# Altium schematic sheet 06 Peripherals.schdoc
size 400 x 277 mm; Device: default420x297; Symbol: default420x297; Name: default420x297; Size: "A3"; Id: /; File: 06 Peripherals; Sheet: /
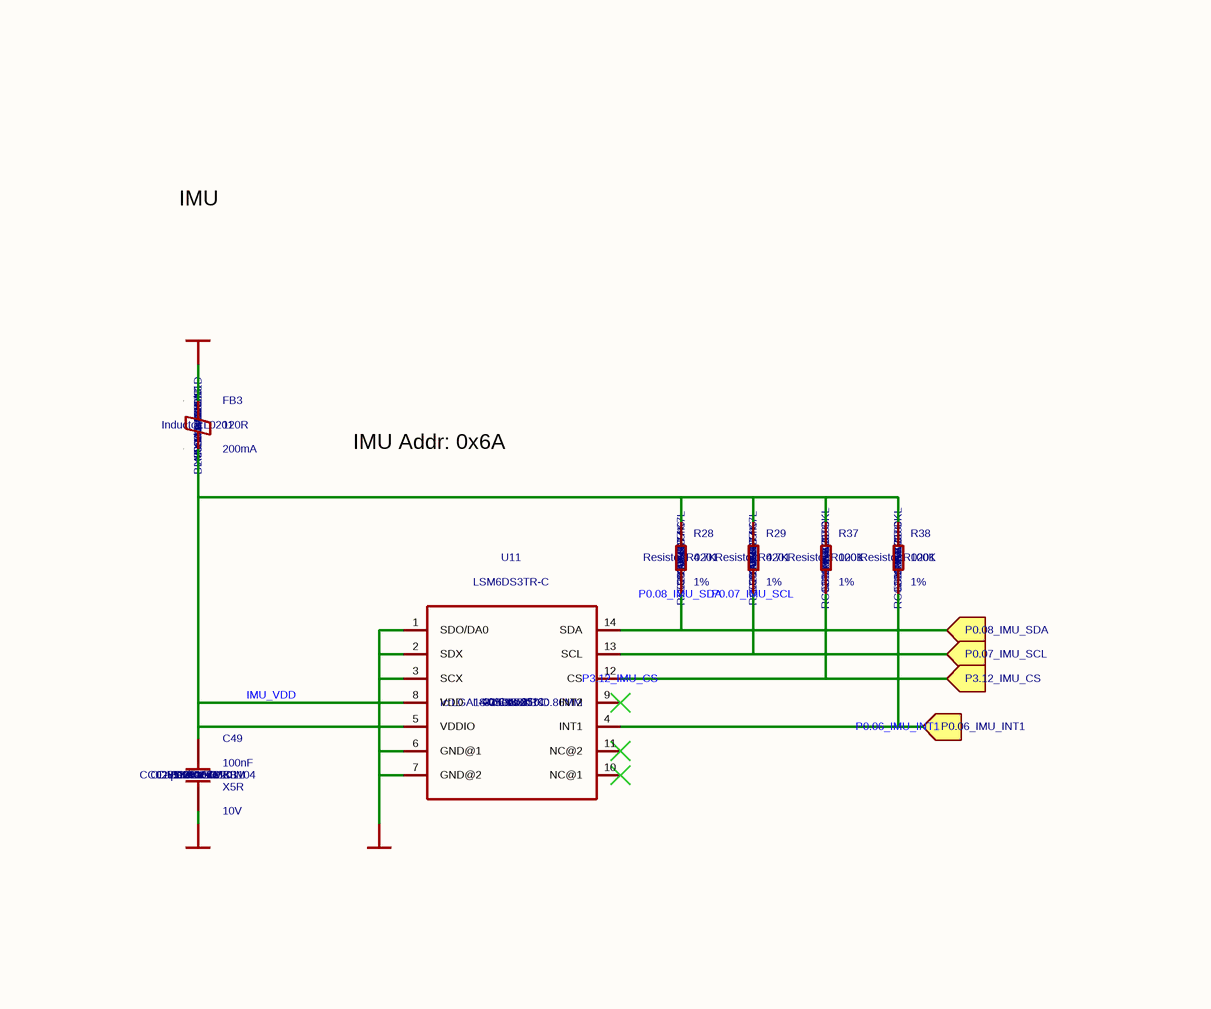
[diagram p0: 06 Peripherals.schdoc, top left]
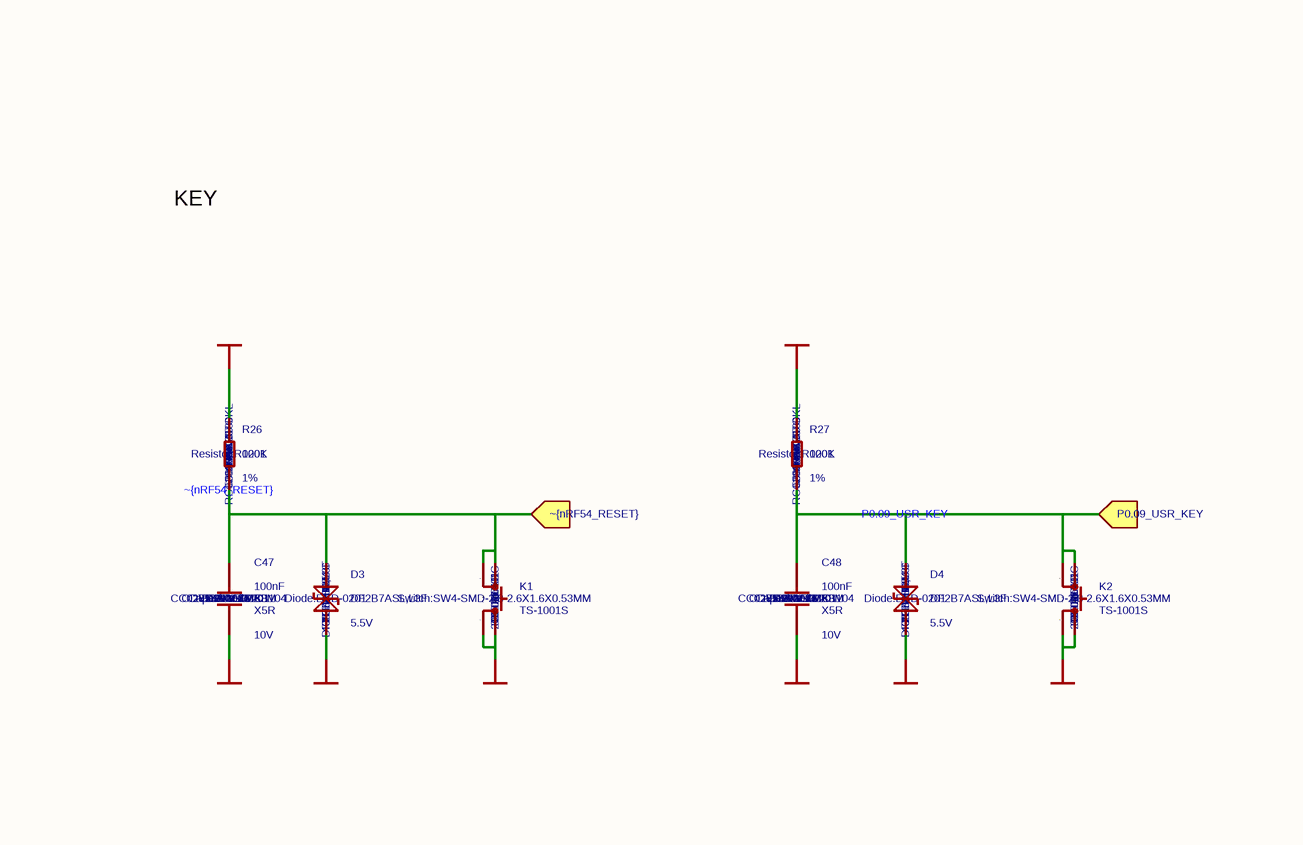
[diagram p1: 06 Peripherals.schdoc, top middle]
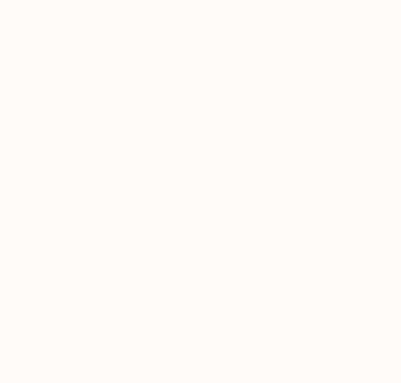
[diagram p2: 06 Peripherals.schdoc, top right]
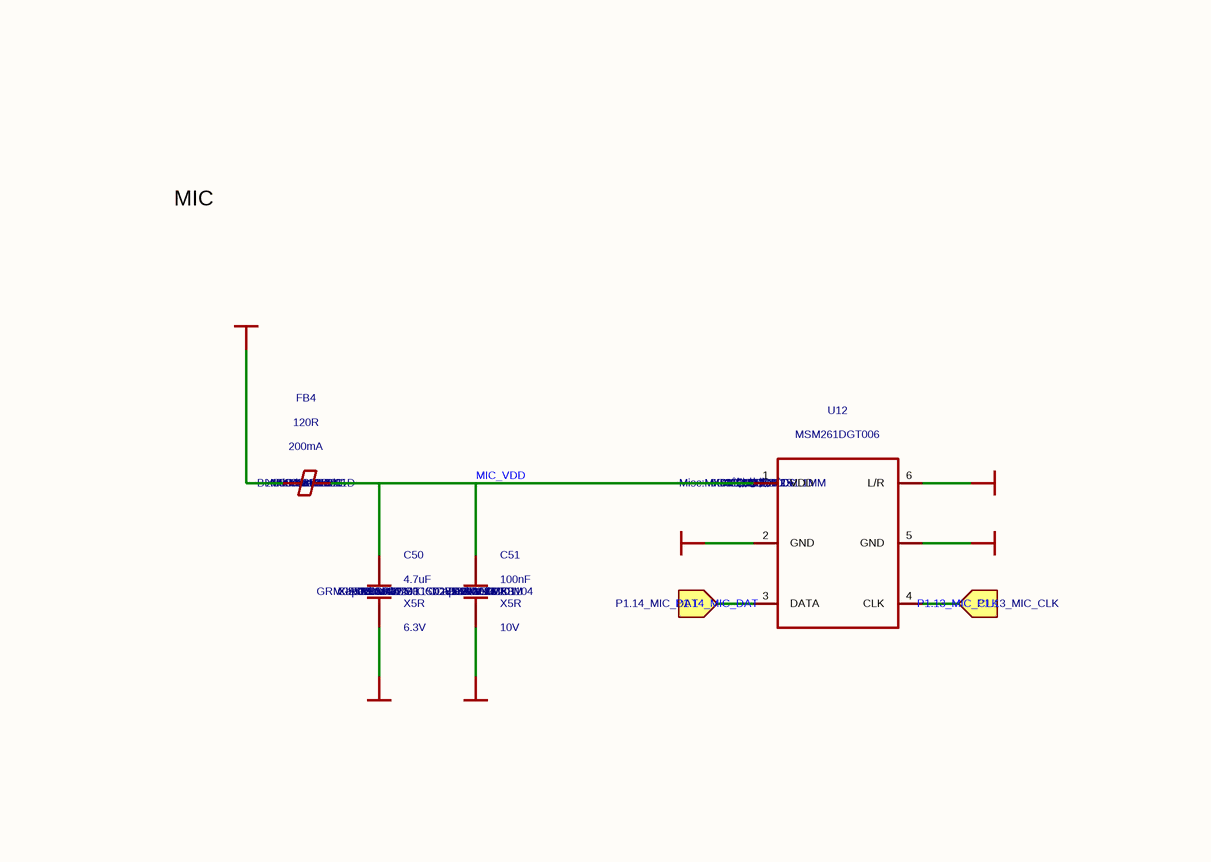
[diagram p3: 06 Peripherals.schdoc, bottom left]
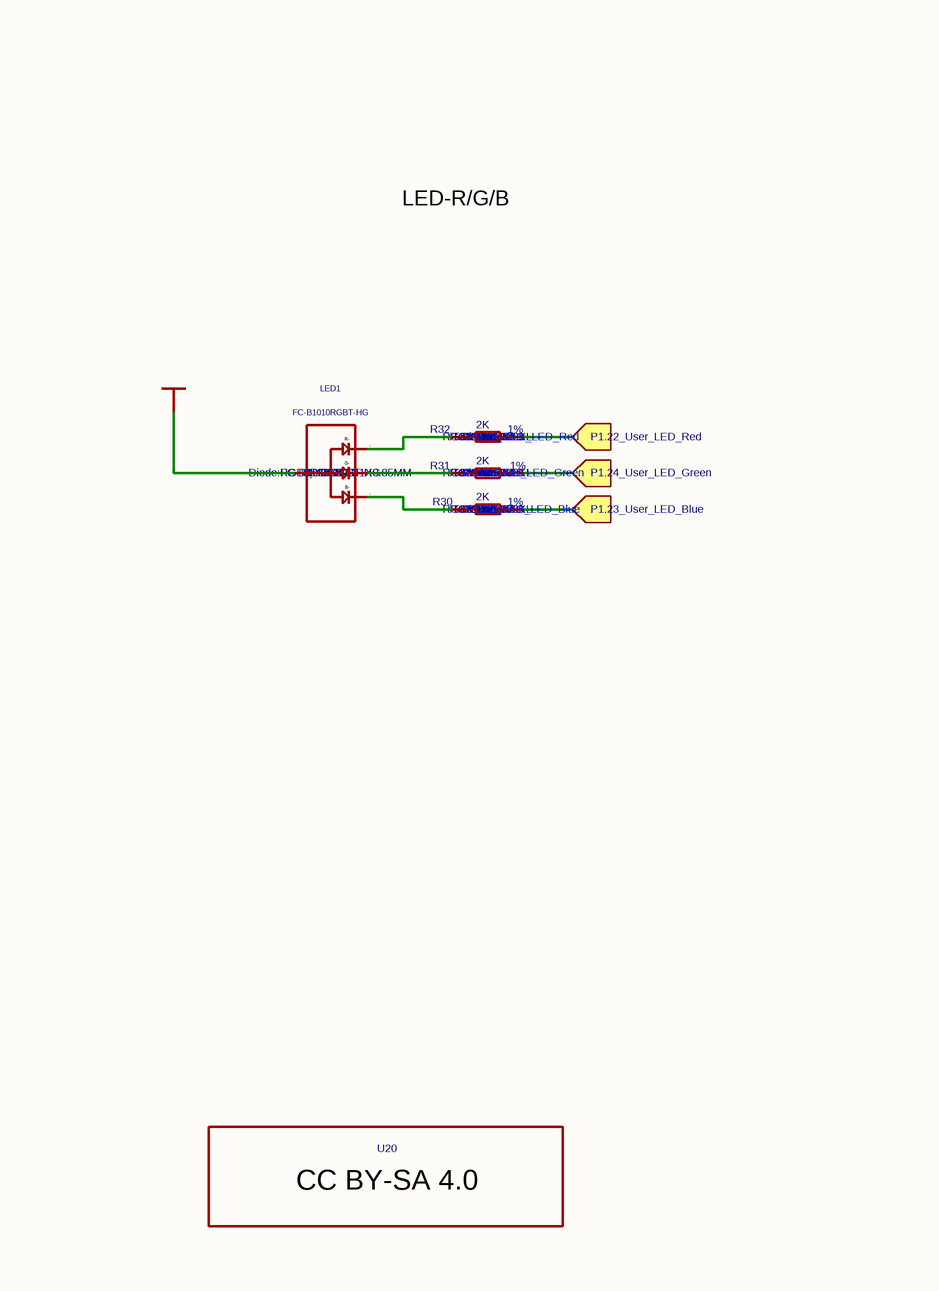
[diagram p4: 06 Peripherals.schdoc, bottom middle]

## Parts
C47  value 100nF  Manufacturer: YAGEO  MPN: CC0201KRX5R6BB104  SKU: 302010271  Dielectric: X5R  Part Type: Ceramic  Voltage Rating: 10V  Status: ODYSSEY-i.MX8M  Temperature: -55°C to 85°C  [Capacitor:C0201]  (hidden comment: Seeed_libdb_Capacitors/CA201100NF-SQS4XQ)
C48  value 100nF  Manufacturer: YAGEO  MPN: CC0201KRX5R6BB104  SKU: 302010271  Dielectric: X5R  Part Type: Ceramic  Voltage Rating: 10V  Status: ODYSSEY-i.MX8M  Temperature: -55°C to 85°C  [Capacitor:C0201]  (hidden comment: Seeed_libdb_Capacitors/CA201100NF-SQS4XQ)
C49  value 100nF  Manufacturer: YAGEO  MPN: CC0201KRX5R6BB104  SKU: 302010271  Dielectric: X5R  Part Type: Ceramic  Voltage Rating: 10V  Status: ODYSSEY-i.MX8M  Temperature: -55°C to 85°C  [Capacitor:C0201]  (hidden comment: Seeed_libdb_Capacitors/CA201100NF-SQS4XQ)
C50  value 4.7uF  Manufacturer: Murata  MPN: GRM035R60J475ME15D  SKU: 302013247  Dielectric: X5R  Part Type: Ceramic  Voltage Rating: 6.3V  Status: XIAO ESP32 S3  Temperature: -55°C to 85°C  [Capacitor:C0201]  (hidden comment: Seeed_libdb_Capacitors/CA20147UF0-SN7236)
C51  value 100nF  Manufacturer: YAGEO  MPN: CC0201KRX5R6BB104  SKU: 302010271  Dielectric: X5R  Part Type: Ceramic  Voltage Rating: 10V  Status: ODYSSEY-i.MX8M  Temperature: -55°C to 85°C  [Capacitor:C0201]  (hidden comment: Seeed_libdb_Capacitors/CA201100NF-SQS4XQ)
D3  value DF2B7ASL,L3F  Manufacturer: TOSHIBA  SKU: 304060494  Part Type: ESD  Rating: 5.5V  Temperature: -40°C to 125°C  [Diode:ESD-0201]  (hidden comment: Seeed_libdb_Diode/DI201DF2B7-5S4UTU)
D4  value DF2B7ASL,L3F  Manufacturer: TOSHIBA  SKU: 304060494  Part Type: ESD  Rating: 5.5V  Temperature: -40°C to 125°C  [Diode:ESD-0201]  (hidden comment: Seeed_libdb_Diode/DI201DF2B7-5S4UTU)
FB3  value 120R  Manufacturer: Murata  MPN: BLM03AG121SN1D  SKU: 303030259  Part Type: Ferrite Bead  Rating: 200mA  Status: XIAO nRF54L15  Temperature: -55°C to 125°C  [Inductor:L0201]  (hidden comment: Seeed_libdb_Ferrite Bead/FB201120R0-7K43FG)
FB4  value 120R  Manufacturer: Murata  MPN: BLM03AG121SN1D  SKU: 303030259  Part Type: Ferrite Bead  Rating: 200mA  Status: XIAO nRF54L15  Temperature: -55°C to 125°C  [Inductor:L0201]  (hidden comment: Seeed_libdb_Ferrite Bead/FB201120R0-7K43FG)
K1  value TS-1001S  Manufacturer: JINBEILI  SKU: 311021801  Part Type: Button  Temperature: -20°C to 70°C  [Switch:SW4-SMD-2.8-2.6X1.6X0.53MM]  (hidden comment: Seeed_libdb_Switch/SW400TS100-LJTNPH)
K2  value TS-1001S  Manufacturer: JINBEILI  SKU: 311021801  Part Type: Button  Temperature: -20°C to 70°C  [Switch:SW4-SMD-2.8-2.6X1.6X0.53MM]  (hidden comment: Seeed_libdb_Switch/SW400TS100-LJTNPH)
LED1  value FC-B1010RGBT-HG  Manufacturer: GUOXING  SKU: 304091787  Part Type: RGB  [Diode:RGB4P-0.65-1X1X0.85MM]  (hidden comment: Seeed_libdb_Diode/DI400FCB10-KTJ2AN)
R26  value 100K  Manufacturer: YAGEO  MPN: RC0201FR-07100KL  SKU: 301010765  Tolerance: 1%  Part Type: RES  Status: XIAO  Temperature: -55°C to 125°C  [Resistor:R0201]  (hidden comment: Seeed_libdb_Resistors/RE201100K0-XFHWYX)
R27  value 100K  Manufacturer: YAGEO  MPN: RC0201FR-07100KL  SKU: 301010765  Tolerance: 1%  Part Type: RES  Status: XIAO  Temperature: -55°C to 125°C  [Resistor:R0201]  (hidden comment: Seeed_libdb_Resistors/RE201100K0-XFHWYX)
R28  value 4.7K  Manufacturer: YAGEO  MPN: RC0201JR-074K7L  SKU: 301010677  Tolerance: 1%  Part Type: RES  Status: XIAO  Temperature: -55°C to 125°C  [Resistor:R0201]  (hidden comment: Seeed_libdb_Resistors/RE20147K00-2N4EPM)
R29  value 4.7K  Manufacturer: YAGEO  MPN: RC0201JR-074K7L  SKU: 301010677  Tolerance: 1%  Part Type: RES  Status: XIAO  Temperature: -55°C to 125°C  [Resistor:R0201]  (hidden comment: Seeed_libdb_Resistors/RE20147K00-2N4EPM)
R30  value 2K  Manufacturer: YAGEO  MPN: RC0201FR-072KL  SKU: 301010754  Tolerance: 1%  Part Type: RES  Status: Recamera  Temperature: -55°C to 125°C  [Resistor:R0201]  (hidden comment: Seeed_libdb_Resistors/RE2012K000-T9Y7X8)
R31  value 2K  Manufacturer: YAGEO  MPN: RC0201FR-072KL  SKU: 301010754  Tolerance: 1%  Part Type: RES  Status: Recamera  Temperature: -55°C to 125°C  [Resistor:R0201]  (hidden comment: Seeed_libdb_Resistors/RE2012K000-T9Y7X8)
R32  value 2K  Manufacturer: YAGEO  MPN: RC0201FR-072KL  SKU: 301010754  Tolerance: 1%  Part Type: RES  Status: Recamera  Temperature: -55°C to 125°C  [Resistor:R0201]  (hidden comment: Seeed_libdb_Resistors/RE2012K000-T9Y7X8)
R37  value 100K  Manufacturer: YAGEO  MPN: RC0201FR-07100KL  SKU: 301010765  Tolerance: 1%  Part Type: RES  Status: XIAO  Temperature: -55°C to 125°C  [Resistor:R0201]  (hidden comment: Seeed_libdb_Resistors/RE201100K0-XFHWYX)
R38  value 100K  Manufacturer: YAGEO  MPN: RC0201FR-07100KL  SKU: 301010765  Tolerance: 1%  Part Type: RES  Status: XIAO  Temperature: -55°C to 125°C  [Resistor:R0201]  (hidden comment: Seeed_libdb_Resistors/RE201100K0-XFHWYX)
U11  value LSM6DS3TR-C  Manufacturer: ST  SKU: 314040211  Part Type: Sensor  Temperature: -40℃ to 85℃  [Ic:LGA14-0.5-2.5X3X0.86MM]  (hidden comment: Seeed_libdb_Ic/IC140LSM6D-63RYKL)
U12  value MSM261DGT006  Manufacturer: 敏芯微  SKU: 312030722  Part Type: MIC  Status: XIAO nRF54L15  Temperature: -40˚C to 100˚C  [Misc:MIC6P-0.94-4X2X1.1MM]  (hidden comment: Seeed_libdb_Misc/MI600MSM26-GPMFAL)
U20  Misc_LOGO_CC_BY-SA_4.0  [Misc:LOGO_CC_BY-SA_4.0]  (value not drawn)

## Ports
P0.06_IMU_INT1 (in), P0.07_IMU_SCL (in), P0.08_IMU_SDA (in), P0.09_USR_KEY (in), P1.13_MIC_CLK (in), P1.14_MIC_DAT (in), P1.22_User_LED_Red (in), P1.23_User_LED_Blue (in), P1.24_User_LED_Green (in), P3.12_IMU_CS (in), ~{nRF54_RESET} (in)

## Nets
power_+5V: FB3.2 FB4.2 LED1.1(+) R26.2 R27.2
Power_Gnd_GNDREF: C47.2 C48.2 C49.2 C50.2 C51.2 D3.1 D4.1 K1.3(B0) K1.4(B1) K2.3(B0) K2.4(B1) U11.1(SDO/DA0) U11.2(SDX) U11.3(SCX) U11.6(GND@1) U11.7(GND@2) U12.2(GND) U12.5(GND) U12.6(L/R)
IMU_VDD: C49.1 FB3.1 R28.2 R29.2 R37.2 R38.2 U11.5(VDDIO) U11.8(VDD)
MIC_VDD: C50.1 C51.1 FB4.1 U12.1(VDD)
P0.06_IMU_INT1: R38.1 U11.4(INT1) ; port P0.06_IMU_INT1
P0.07_IMU_SCL: R29.1 U11.13(SCL) ; port P0.07_IMU_SCL
P0.08_IMU_SDA: R28.1 U11.14(SDA) ; port P0.08_IMU_SDA
P0.09_USR_KEY: C48.1 D4.2 K2.1(A0) K2.2(A1) R27.1 ; port P0.09_USR_KEY
P1.13_MIC_CLK: U12.4(CLK) ; port P1.13_MIC_CLK
P1.14_MIC_DAT: U12.3(DATA) ; port P1.14_MIC_DAT
P1.22_User_LED_Red: R32.2 ; port P1.22_User_LED_Red
P1.23_User_LED_Blue: R30.2 ; port P1.23_User_LED_Blue
P1.24_User_LED_Green: R31.2 ; port P1.24_User_LED_Green
P3.12_IMU_CS: R37.1 U11.12(CS) ; port P3.12_IMU_CS
~{nRF54_RESET}: C47.1 D3.2 K1.1(A0) K1.2(A1) R26.1 ; port ~{nRF54_RESET}
NetLED1_2: LED1.2(R-) R32.1
NetLED1_3: LED1.3(G-) R31.1
NetLED1_4: LED1.4(B-) R30.1

Not connected (* = marked no-connect by the designer): U11 9(INT2)* 10(NC@1)* 11(NC@2)*

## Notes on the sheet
- IMU
- KEY
- IMU Addr: 0x6A
- MIC
- LED-R/G/B

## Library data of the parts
C47 = Seeed_libdb_Capacitors/CA201100NF-SQS4XQ: SMD CAP Ceramic 100nF-10V-10%-X5R;0201; UniqueId: 64621f1995cfd5bc; AddInBom: yes
C48 = Seeed_libdb_Capacitors/CA201100NF-SQS4XQ: SMD CAP Ceramic 100nF-10V-10%-X5R;0201; UniqueId: 808ebf677d8d6d64; AddInBom: yes
C49 = Seeed_libdb_Capacitors/CA201100NF-SQS4XQ: SMD CAP Ceramic 100nF-10V-10%-X5R;0201; UniqueId: 91fd74edebd22ea1; AddInBom: yes
C50 = Seeed_libdb_Capacitors/CA20147UF0-SN7236: SMD CAP Ceramic 4.7uF-6.3V-20%-X5R;0201; UniqueId: 32f6df7045cd6eaa; AddInBom: yes
C51 = Seeed_libdb_Capacitors/CA201100NF-SQS4XQ: SMD CAP Ceramic 100nF-10V-10%-X5R;0201; UniqueId: d35436b77a732af0; AddInBom: yes
D3 = Seeed_libdb_Diode/DI201DF2B7-5S4UTU: SMD Diode ESD 5.5V-6V-12pF-30KV-30KV;X1SON(2); UniqueId: 81689f1d3303caec; AddInBom: yes
D4 = Seeed_libdb_Diode/DI201DF2B7-5S4UTU: SMD Diode ESD 5.5V-6V-12pF-30KV-30KV;X1SON(2); UniqueId: 6a4368da87585c93; AddInBom: yes
FB3 = Seeed_libdb_Ferrite Bead/FB201120R0-7K43FG: SMD Ferrite Bead 120R-200mA;0201; UniqueId: a866da50d69e2281; AddInBom: yes
FB4 = Seeed_libdb_Ferrite Bead/FB201120R0-7K43FG: SMD Ferrite Bead 120R-200mA;0201; UniqueId: e8ffa92654205bd5; AddInBom: yes
K1 = Seeed_libdb_Switch/SW400TS100-LJTNPH: SMD Top Button 163gf:4P-2.6*1.6*0.53mm; UniqueId: 4da78d22c74f1c2b; AddInBom: yes
K2 = Seeed_libdb_Switch/SW400TS100-LJTNPH: SMD Top Button 163gf:4P-2.6*1.6*0.53mm; UniqueId: c367b9aa41be0627; AddInBom: yes
LED1 = Seeed_libdb_Diode/DI400FCB10-KTJ2AN: SMD LED RGB;4P-L1.0*W1.0*H0.85mm; UniqueId: 7a65b453ee5a9ec2; AddInBom: yes
R26 = Seeed_libdb_Resistors/RE201100K0-XFHWYX: SMD RES 100K-±1%-1/20W;0201; UniqueId: 09b823a69019dbbf; AddInBom: yes
R27 = Seeed_libdb_Resistors/RE201100K0-XFHWYX: SMD RES 100K-±1%-1/20W;0201; UniqueId: 28145adf450505d9; AddInBom: yes
R28 = Seeed_libdb_Resistors/RE20147K00-2N4EPM: SMD RES;4.7K-5%-1/20W;0201; UniqueId: d9f908b8ca857374; AddInBom: yes
R29 = Seeed_libdb_Resistors/RE20147K00-2N4EPM: SMD RES;4.7K-5%-1/20W;0201; UniqueId: 9e71ce6b7342da3b; AddInBom: yes
R30 = Seeed_libdb_Resistors/RE2012K000-T9Y7X8: SMD RES 2K-1%-1/20W;0201; UniqueId: 8a972535593efa61; AddInBom: yes
R31 = Seeed_libdb_Resistors/RE2012K000-T9Y7X8: SMD RES 2K-1%-1/20W;0201; UniqueId: b304d0fb6138316f; AddInBom: yes
R32 = Seeed_libdb_Resistors/RE2012K000-T9Y7X8: SMD RES 2K-1%-1/20W;0201; UniqueId: 94189e0415d5623f; AddInBom: yes
R37 = Seeed_libdb_Resistors/RE201100K0-XFHWYX: SMD RES 100K-±1%-1/20W;0201; UniqueId: 0e69257913149112; AddInBom: yes
R38 = Seeed_libdb_Resistors/RE201100K0-XFHWYX: SMD RES 100K-±1%-1/20W;0201; UniqueId: 2eb3813281b987ab; AddInBom: yes
U11 = Seeed_libdb_Ic/IC140LSM6D-63RYKL: SMD 6 Axis  Acceleration Sensor;LGA-14L; UniqueId: 2fd166bdb6936536; AddInBom: yes
U12 = Seeed_libdb_Misc/MI600MSM26-GPMFAL: SMD DIGITAL MIC OMNI -26dBFS;LGA-6:4*2*1.1mm; UniqueId: b6112465b0588c80; AddInBom: yes
U20 = Misc_LOGO_CC_BY-SA_4.0: UniqueId: bbc2f931070973b7; AddInBom: yes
